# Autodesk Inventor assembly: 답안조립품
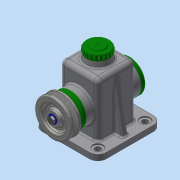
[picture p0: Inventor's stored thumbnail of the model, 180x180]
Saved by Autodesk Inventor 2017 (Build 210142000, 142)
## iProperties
Part Number: 답안조립품
Material: 일반
Document SubType Name: Assembly
Designer: MRC
Author: MRC
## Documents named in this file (14)
- C:\Users\MRC\Desktop\700907V1002\답안조립품.iam
- C:\Users\MRC\Desktop\700907V1002\V-벨트풀리.ipt
- C:\Users\MRC\Desktop\700907V1002\뒤커버.ipt
- C:\Users\MRC\Desktop\700907V1002\멈춤링 15 x 1.ipt
- C:\Users\MRC\Desktop\700907V1002\베어링 15 x 35 x 11.ipt
- C:\Users\MRC\Desktop\700907V1002\본체.ipt
- C:\Users\MRC\Desktop\700907V1002\볼트 M4 x 10.ipt
- C:\Users\MRC\Desktop\700907V1002\볼트 M6 x 12.ipt
- C:\Users\MRC\Desktop\700907V1002\상부캡.ipt
- C:\Users\MRC\Desktop\700907V1002\앞커버.ipt
- C:\Users\MRC\Desktop\700907V1002\오일실 15 25 7.ipt
- C:\Users\MRC\Desktop\700907V1002\와셔.ipt
- C:\Users\MRC\Desktop\700907V1002\축.ipt
- C:\Users\MRC\Desktop\700907V1002\키 5 x 5 x 14.ipt
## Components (1 placed, 1 different names)
1. V-벨트풀리:1
